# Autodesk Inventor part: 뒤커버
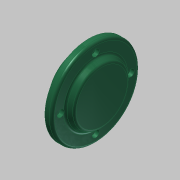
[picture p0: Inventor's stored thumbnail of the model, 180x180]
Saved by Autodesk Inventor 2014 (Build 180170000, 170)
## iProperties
Created: 2015-11
Part Number: 뒤커버
Material: 일반
Document SubType Name: Modeling
Designer: mduedu
Density: 1 g/cm^3
Appearance: 매끄러움 - 짙은 바다 녹색
Mass: 114.065 g
Surface Area: 231.216 cm^2
Volume: 114.065 cm^3
Author: mduedu
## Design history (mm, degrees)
sketch "스케치1"
  geometry: C1 r 50 at (0, 0); 1 further point
  constraints: 1 centre point, 1 coincident
  dimensions: "d42" = 100 diameter of C1
extrude "돌출1" new body sketch "스케치1" distance "d3" = 8; taper "d4" = 0 deg
sketch "스케치2"
  geometry: C1 r 35 at (0, 0); 1 further point
  constraints: 1 centre point, 1 coincident
  dimensions: "d5" = 70 diameter of C1
extrude "돌출2" join sketch "스케치2" distance "d6" = 7; taper "d7" = -30 deg
sketch "스케치5" dims "d44" = 80
  geometry: 3 further points
  constraints: 2 vertical alignment, 1 coincident, 2 other
hole "구멍3" sketch "스케치5" at (0, 40) diameter "d45" = 4.5; stored, may be unused: countersink angle "d49" = 90 deg, drill point angle "d51" = 118 deg; dims "d46" = 6, "d47" = 8, "d48" = 4.4, "d50" = 8
sketch "스케치4"
  geometry: C1 r 35 at (0, 0); 1 further point
  constraints: 1 centre point, 1 coincident
  dimensions: "d21" = 70 diameter of C1
extrude "돌출3" join sketch "스케치4" distance "d23" = 12; taper "d24" = 0 deg
hole "구멍2" diameter "d27" = 30; stored, may be unused: countersink angle "d31" = 90 deg, drill point angle "d33" = 0 deg; dims "d25" = 10, "d26" = 10, "d28" = 6, "d29" = 40, "d30" = 12, "d32" = 15
fillet "모깎기3" dims "d36" = 3
fillet "모깎기4" dims "d37" = 3
fillet "모깎기5" dims "d38" = 0.3
chamfer "모따기1" distance "d39" = 1; stored, may be unused: second distance "d40" = 2, angle "d41" = 45 deg
node "솔리드1"
pattern_circular "원형 패턴2" dims angle "d53" = 360 deg
